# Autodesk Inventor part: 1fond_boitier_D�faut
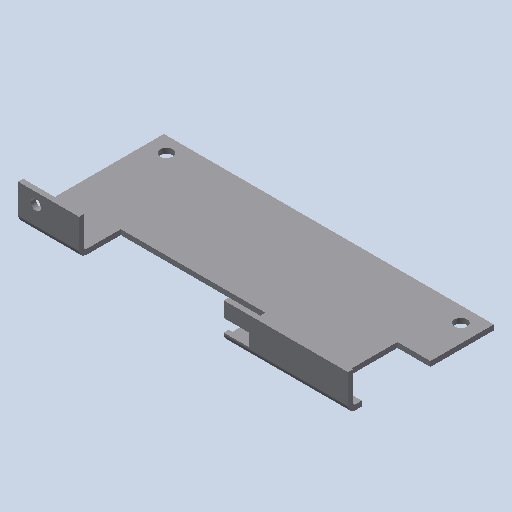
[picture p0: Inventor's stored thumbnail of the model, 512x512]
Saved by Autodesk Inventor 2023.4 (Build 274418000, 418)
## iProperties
Created: 2011-01
Part Number: 1fond_boitier_D�faut
Document SubType Name: Modeling
Designer: eric
Density: 1 g/cm^3
Mass: 13.8423 g
Surface Area: 149.303 cm^2
Volume: 13.8423 cm^3
Material: Générique
Appearance: Par défaut
Author: eric
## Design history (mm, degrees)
feature "Base1"
node "Corps solides"
node "Corps surfaciques"
node "Solide1"
